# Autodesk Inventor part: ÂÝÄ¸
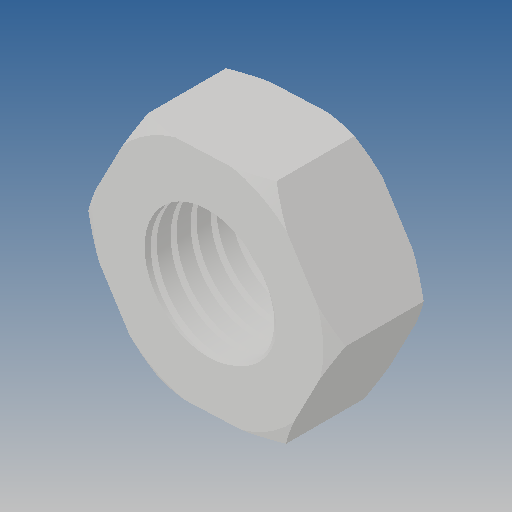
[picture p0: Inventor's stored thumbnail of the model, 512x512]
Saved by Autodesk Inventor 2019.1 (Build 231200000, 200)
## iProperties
Created: 2012-10
Part Number: ÂÝÄ¸
Material: Ogólny
Document SubType Name: Modeling
Designer: CADENGINEERING4
Density: 1 g/cm^3
Appearance: Domyślna
Author: CADENGINEERING4
Revision Number: ÈÎºÎ
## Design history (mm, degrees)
feature "ÇÐ³ý-É¨Ãè1"
node "Bryła1"
